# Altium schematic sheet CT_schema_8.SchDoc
size 386 x 278 mm
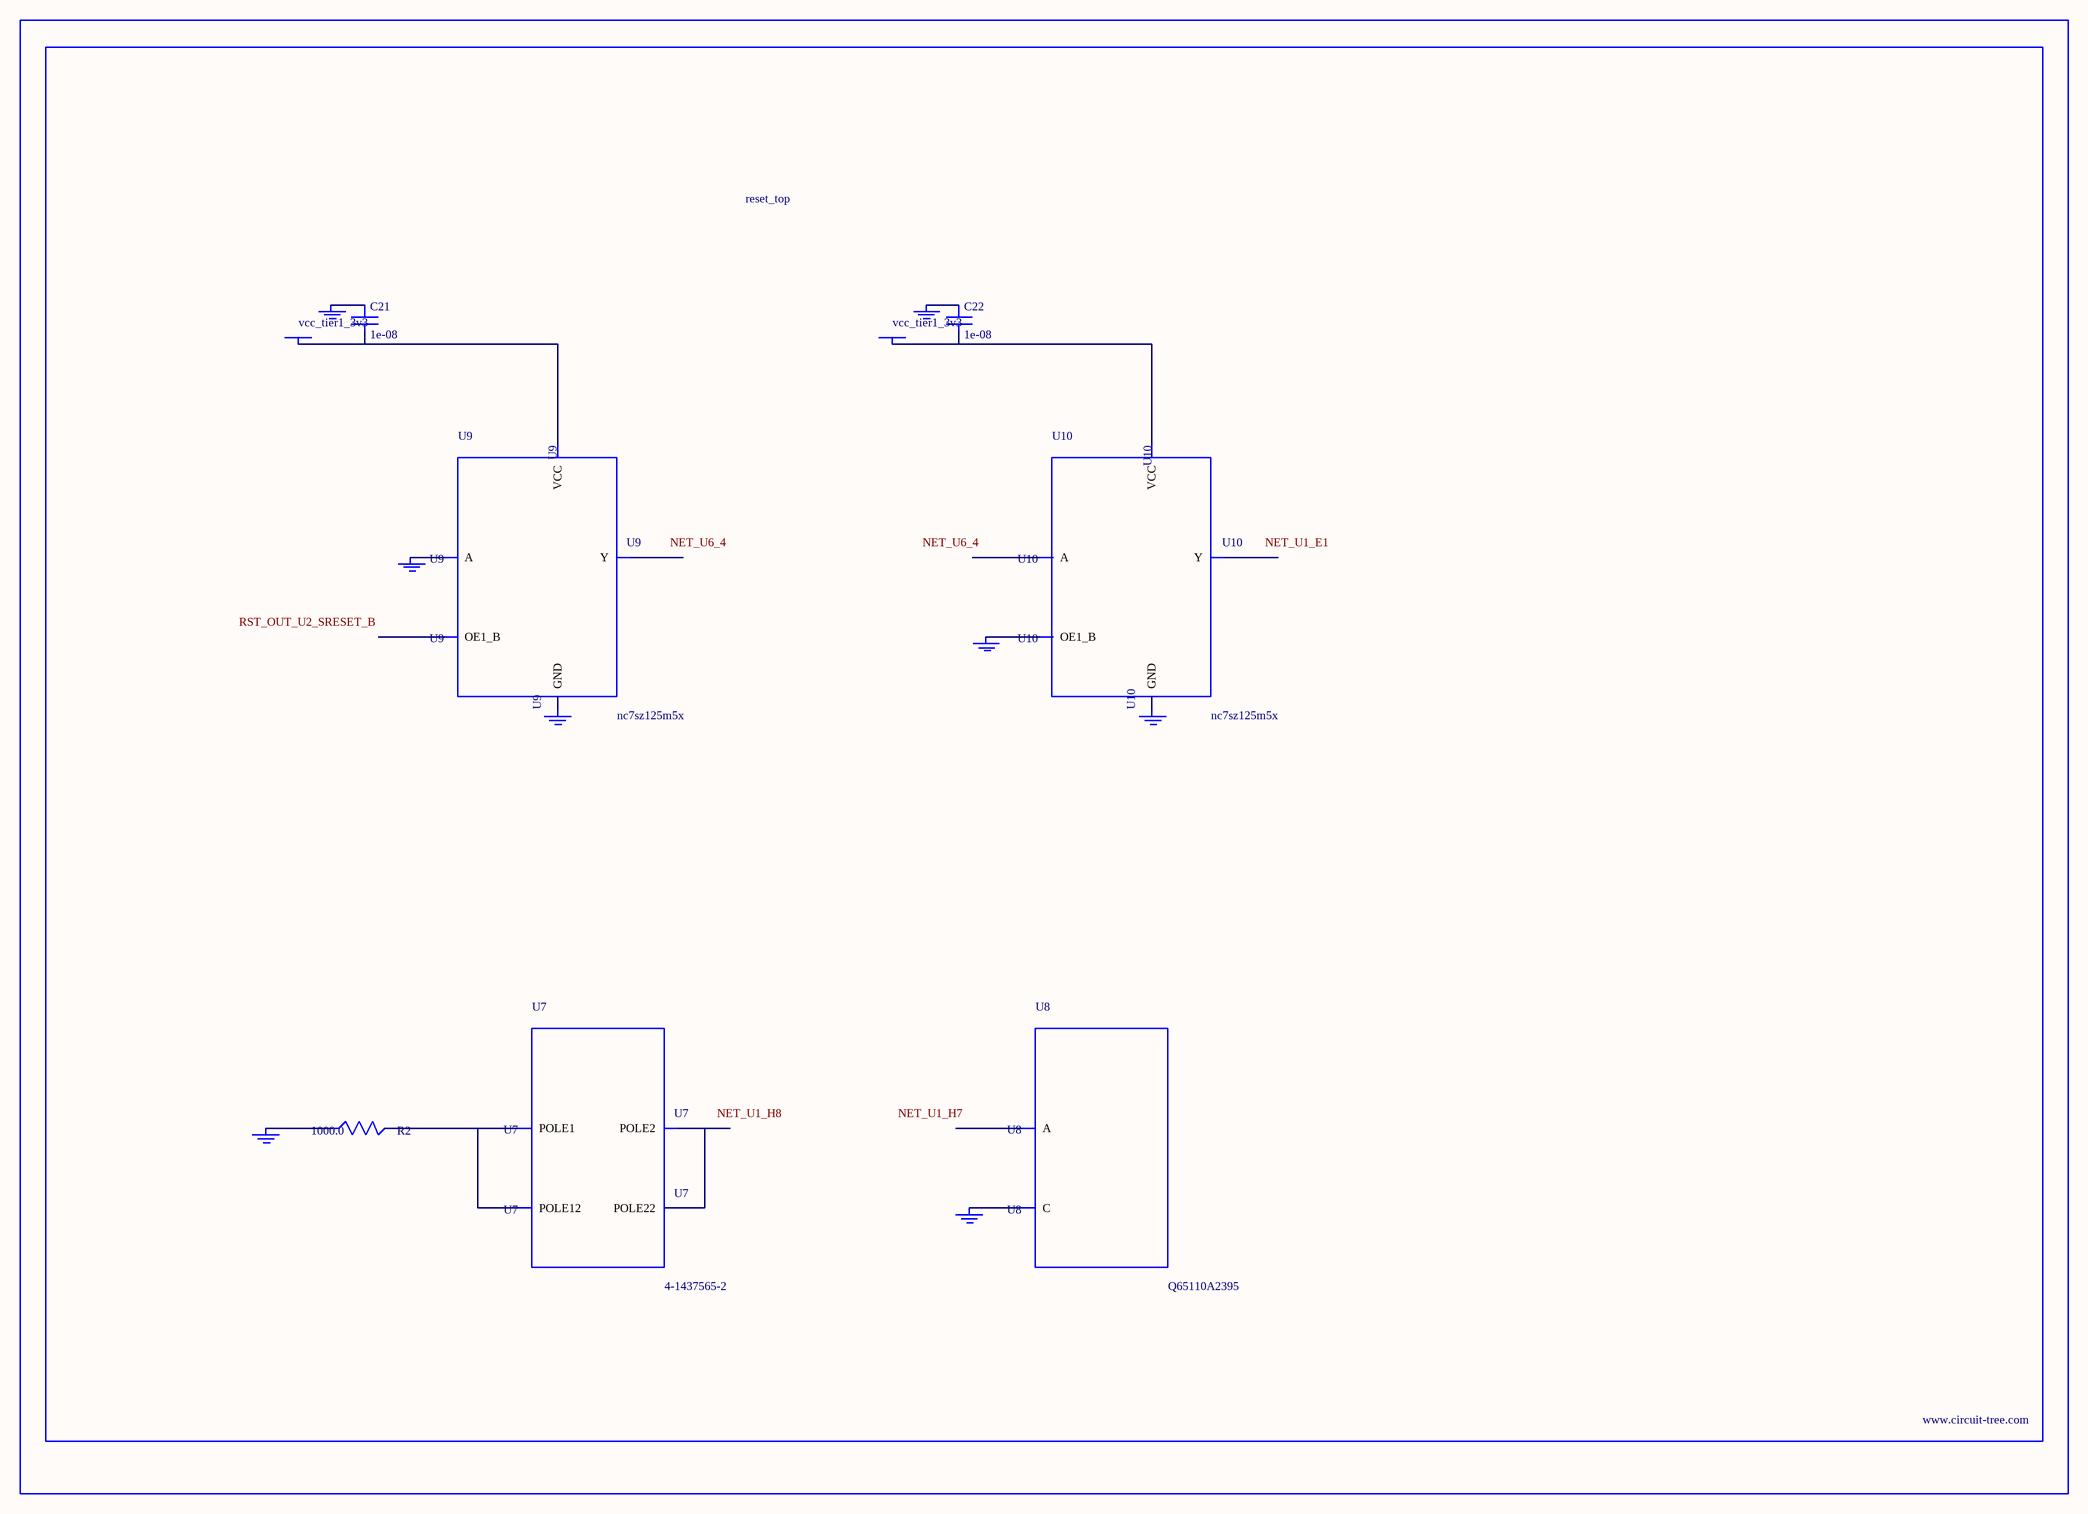
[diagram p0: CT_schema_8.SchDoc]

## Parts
BORDER7  (no value)
C21  1e-08  [C0402]
C22  1e-08  [C0402]
GND_INSTANCE_7_0  (no value)
GND_INSTANCE_7_1  (no value)
GND_INSTANCE_7_2  (no value)
GND_INSTANCE_7_3  (no value)
GND_INSTANCE_7_4  (no value)
GND_INSTANCE_7_5  (no value)
GND_INSTANCE_7_6  (no value)
GND_INSTANCE_7_7  (no value)
POWER_INSTANCE_7_0  vcc_tier1_3v3
POWER_INSTANCE_7_1  vcc_tier1_3v3
R2  1000.0  [R0603]
U7  4-1437565-2  [SW_4-1437565-2]
U8  Q65110A2395  [LGM67K-G1J2-24-Z]
U9  nc7sz125m5x  [NC7SZ125M5X]
U10  nc7sz125m5x  [NC7SZ125M5X]

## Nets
NetC21_1: C21.1 GND_INSTANCE_7_2.0(GND)
NetC21_2: C21.2 POWER_INSTANCE_7_0.0(PWR) U9.5(VCC)
NetC22_1: C22.1 GND_INSTANCE_7_5.0(GND)
NetC22_2: C22.2 POWER_INSTANCE_7_1.0(PWR) U10.5(VCC)
NetGND_INSTANCE_7_0_0: GND_INSTANCE_7_0.0(GND) R2.1
NetGND_INSTANCE_7_1_0: GND_INSTANCE_7_1.0(GND) U8.C
NetGND_INSTANCE_7_3_0: GND_INSTANCE_7_3.0(GND) U9.2(A)
NetGND_INSTANCE_7_4_0: GND_INSTANCE_7_4.0(GND) U9.3(GND)
NetGND_INSTANCE_7_6_0: GND_INSTANCE_7_6.0(GND) U10.1(OE1_B)
NetGND_INSTANCE_7_7_0: GND_INSTANCE_7_7.0(GND) U10.3(GND)
NetR2_2: R2.2 U7.1(POLE1) U7.2(POLE12)
NetU7_3: U7.3(POLE2) U7.4(POLE22)

Not connected (* = marked no-connect by the designer): U8 A; U9 1(OE1_B) 4(Y); U10 2(A) 4(Y)

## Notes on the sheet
- Labels drawn without touching a wire or pin: NET_U1_E1, NET_U1_H7, NET_U1_H8, NET_U6_4, RST_OUT_U2_SRESET_B

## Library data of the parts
BORDER7 = BORDER_PAGE7
C21 C22 = C0402C103K3RAC
GND_INSTANCE_7_0-GND_INSTANCE_7_7 = GND
POWER_INSTANCE_7_0 POWER_INSTANCE_7_1 = PWR
R2 = RC0603JR-071KL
